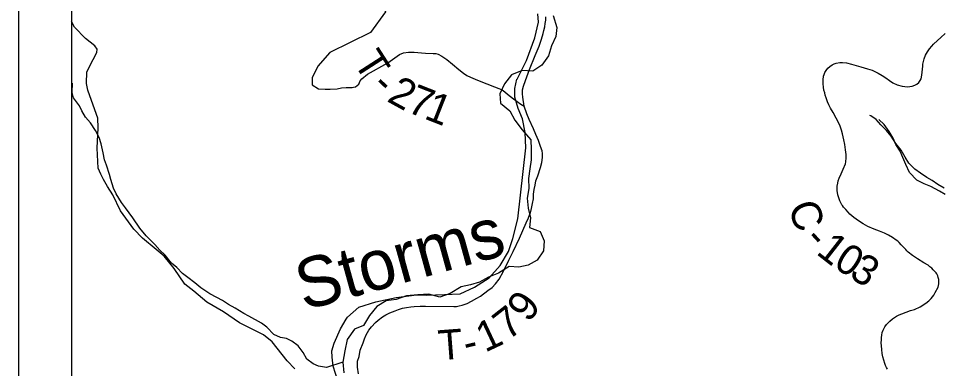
# Model space of a CAD drawing. Extents: x 0 to 34, y 0 to 22.
# Drawn here: x 2 to 3.746, y 18.72 to 19.381 of the extents above; entities that cross this region are included whole.
import ezdxf

# ---------------------------------------------------------------- set-up
doc = ezdxf.new("R2010")
doc.units = 0
for name, color, linetype in [('GM_X_County_Road', 7, 'Continuous'), ('GM_X_County_Road_Text', 7, 'Continuous'), ('GM_X_Minor_River', 7, 'Continuous'), ('GM_X_Minor_River_Text', 7, 'Continuous'), ('GM_X_Rail_Line', 7, 'Continuous'), ('GM_X_Township_Road', 7, 'Continuous'), ('GM_X_Township_Road_Text', 7, 'Continuous'), ('SH_Data', 7, 'Continuous')]:
    doc.layers.add(name, color=color, linetype=linetype)

msp = doc.modelspace()

# ---------------------------------------------------------------- linework, layer by layer
at = {"layer": 'GM_X_County_Road'}
for points in [[(2.5221, 18.7197), (2.5078, 18.7347), (2.4796, 18.7702), (2.4633, 18.7839), (2.4354, 18.7974), (2.4176, 18.8066), (2.3874, 18.8273), (2.356, 18.8454), (2.3315, 18.866), (2.3145, 18.8794), (2.2942, 18.9088), (2.2751, 18.9321), (2.26, 18.9451), (2.2343, 18.9662), (2.2177, 18.9834), (2.1926, 19.0181), (2.178, 19.0482), (2.1682, 19.0642), (2.1607, 19.0772), (2.1555, 19.0871), (2.1506, 19.0985), (2.149, 19.1365), (2.1503, 19.1749), (2.1501, 19.1931), (2.1411, 19.2178), (2.1311, 19.246), (2.1285, 19.2582), (2.129, 19.2802), (2.1409, 19.3037), (2.1479, 19.3169), (2.1487, 19.3234), (2.1441, 19.3299), (2.1268, 19.3433), (2.1061, 19.365), (2.1, 19.3757)], [(3.6422, 18.7185), (3.6403, 18.7218), (3.6386, 18.726), (3.637, 18.7295), (3.6351, 18.7357), (3.6335, 18.7421), (3.6322, 18.7487), (3.6314, 18.7557), (3.6308, 18.7628), (3.6305, 18.7686), (3.6306, 18.7741), (3.6308, 18.7785), (3.6316, 18.7831), (3.6323, 18.7878), (3.6342, 18.7925), (3.6375, 18.7989), (3.6405, 18.8033), (3.6464, 18.8098), (3.6518, 18.814), (3.6552, 18.8164), (3.6595, 18.8189), (3.6643, 18.8214), (3.6696, 18.8235), (3.6855, 18.8294), (3.6932, 18.8316), (3.7041, 18.8366), (3.7147, 18.8434), (3.7203, 18.8479), (3.7245, 18.8523), (3.7296, 18.8583), (3.7325, 18.8638), (3.7377, 18.8737), (3.7393, 18.8799), (3.7393, 18.8841), (3.739, 18.8882), (3.7382, 18.8921), (3.7372, 18.8953), (3.7354, 18.8991), (3.7339, 18.9011), (3.7313, 18.9037), (3.7286, 18.9066), (3.726, 18.9093), (3.7224, 18.9121), (3.7188, 18.9152), (3.7111, 18.9197), (3.6991, 18.9275), (3.6897, 18.9338), (3.6816, 18.9397), (3.6787, 18.9426), (3.6768, 18.9447), (3.6721, 18.9501), (3.6682, 18.954), (3.6642, 18.9581), (3.6615, 18.9607), (3.6584, 18.9628), (3.6518, 18.9677), (3.6444, 18.9717), (3.6363, 18.9757), (3.6272, 18.9794), (3.6171, 18.9833), (3.6049, 18.9885), (3.5964, 18.9932), (3.5873, 18.9989), (3.5784, 19.0051), (3.571, 19.0119), (3.5678, 19.0152), (3.5633, 19.0202), (3.5594, 19.0247), (3.5573, 19.0277), (3.5561, 19.0294), (3.5522, 19.0371), (3.5507, 19.0407), (3.5483, 19.048), (3.5477, 19.0524), (3.5471, 19.0559), (3.547, 19.0599), (3.5472, 19.0645), (3.5482, 19.0701), (3.5492, 19.0743), (3.5511, 19.0797), (3.5546, 19.0879), (3.5587, 19.0964), (3.5626, 19.1068), (3.5632, 19.1105), (3.5641, 19.118), (3.564, 19.1245), (3.563, 19.1332), (3.5614, 19.1431), (3.5598, 19.1523), (3.5573, 19.1634), (3.555, 19.1704), (3.5521, 19.1796), (3.5455, 19.1929), (3.5396, 19.2036), (3.5346, 19.2116), (3.5316, 19.218), (3.5289, 19.2239), (3.5263, 19.2311), (3.5245, 19.2363), (3.5235, 19.2409), (3.5222, 19.246), (3.5215, 19.2514), (3.5209, 19.2578), (3.5207, 19.2653), (3.5215, 19.2721), (3.5225, 19.2754), (3.524, 19.2791), (3.5261, 19.2832), (3.5296, 19.2872), (3.533, 19.2905), (3.5377, 19.2937), (3.5416, 19.2954), (3.5452, 19.2966), (3.552, 19.2979), (3.557, 19.2984), (3.5647, 19.2976), (3.5744, 19.295), (3.5918, 19.2902), (3.6044, 19.2864), (3.6131, 19.2837), (3.6244, 19.2779), (3.6319, 19.2734), (3.6388, 19.2692), (3.646, 19.2642), (3.6526, 19.2599), (3.6607, 19.2559), (3.6701, 19.2532), (3.68, 19.2522), (3.6889, 19.2534), (3.694, 19.2553), (3.6974, 19.2574), (3.7014, 19.2604), (3.7042, 19.264), (3.7057, 19.2672), (3.7072, 19.2745), (3.7079, 19.2798), (3.7088, 19.2912), (3.7093, 19.2952), (3.7102, 19.3003), (3.7114, 19.3048), (3.7143, 19.3117), (3.7181, 19.3186), (3.7219, 19.3242), (3.7258, 19.329), (3.7294, 19.3326), (3.7366, 19.3398), (3.7429, 19.3456), (3.7509, 19.3528)]]:
    msp.add_lwpolyline(points, dxfattribs=at)
at = {"layer": 'GM_X_Minor_River'}
for points in [[(3.0103, 19.3869), (3.0174, 19.3644), (3.0155, 19.3473), (3.0071, 19.3294), (3.0018, 19.3108), (2.9889, 19.2933), (2.9718, 19.2819), (2.9517, 19.2831), (2.9317, 19.2747), (2.9187, 19.2576), (2.9096, 19.239), (2.9111, 19.2215), (2.9285, 19.207), (2.9383, 19.1891), (2.9519, 19.1709), (2.9685, 19.1518), (2.9688, 19.134), (2.9688, 19.1142), (2.9661, 19.0971), (2.9638, 19.0788), (2.9645, 19.0598), (2.9614, 19.0419), (2.9632, 19.0229), (2.9674, 19.005), (2.9658, 18.9867), (2.9859, 18.9787), (2.9934, 18.9612), (2.9922, 18.9426), (2.9804, 18.9247)], [(2.6132, 18.7321), (2.5822, 18.722), (2.5667, 18.7247), (2.5568, 18.7292), (2.5448, 18.738), (2.5383, 18.7505), (2.5285, 18.763), (2.5168, 18.7717), (2.5066, 18.777), (2.4949, 18.7789), (2.4828, 18.7842), (2.4692, 18.7982), (2.4593, 18.8054), (2.4355, 18.8187), (2.4257, 18.824), (2.4094, 18.8339), (2.3966, 18.8411), (2.3856, 18.8483), (2.3751, 18.8543), (2.3614, 18.8612), (2.3448, 18.8725), (2.3335, 18.882), (2.3199, 18.8919), (2.31, 18.8998), (2.2991, 18.9108), (2.2893, 18.9192), (2.2772, 18.9343), (2.2673, 18.9438), (2.2579, 18.9544), (2.2416, 18.9707), (2.2295, 18.9852), (2.2163, 19.0045), (2.2023, 19.0238), (2.1948, 19.0337), (2.1846, 19.05), (2.1797, 19.061), (2.1744, 19.0773), (2.1721, 19.0868), (2.1661, 19.1042), (2.1623, 19.1145), (2.16, 19.1274), (2.1562, 19.1448), (2.1525, 19.1566), (2.1453, 19.1699), (2.1362, 19.1843), (2.1264, 19.1949), (2.1196, 19.2067), (2.1151, 19.2165), (2.1041, 19.2317), (2.1015, 19.2415), (2.1022, 19.2594)], [(3.7491, 19.0608), (3.7374, 19.0677), (3.7265, 19.0753), (3.7163, 19.0807), (3.7045, 19.0891), (3.694, 19.0967), (3.6823, 19.1077), (3.6755, 19.1191), (3.6683, 19.1324), (3.6581, 19.1454), (3.6491, 19.1591), (3.6404, 19.1697), (3.6298, 19.1804), (3.6208, 19.1903), (3.611, 19.1975), (3.6091, 19.1983)], [(3.751, 19.0488), (3.7405, 19.0552), (3.7242, 19.0639), (3.7117, 19.0692), (3.6977, 19.076), (3.6841, 19.0904), (3.6766, 19.1052), (3.6713, 19.1185), (3.666, 19.1306), (3.6581, 19.1435), (3.6528, 19.1549), (3.6456, 19.1678), (3.6358, 19.1811), (3.6257, 19.1906)], [(2.9804, 18.9247), (2.9634, 18.9152), (2.9456, 18.9118), (2.927, 18.9126), (2.9073, 18.9004), (2.8884, 18.8928), (2.8713, 18.8833), (2.8543, 18.878), (2.8368, 18.8742), (2.816, 18.8617), (2.7963, 18.8549), (2.7755, 18.8602), (2.7547, 18.8595), (2.7331, 18.8576), (2.7138, 18.8504), (2.6948, 18.8477), (2.677, 18.8375), (2.6633, 18.8203), (2.6523, 18.8013), (2.6353, 18.7945), (2.6212, 18.7747), (2.6166, 18.7534), (2.6132, 18.7321), (2.615, 18.7116)]]:
    msp.add_lwpolyline(points, dxfattribs=at)
at = {"layer": 'GM_X_Rail_Line'}
msp.add_lwpolyline([(2.6037, 18.697), (2.5949, 18.7243), (2.5928, 18.7415), (2.5922, 18.7534), (2.5963, 18.7678), (2.6085, 18.7949), (2.6192, 18.813), (2.622, 18.8173), (2.6431, 18.8359), (2.6751, 18.8459), (2.7137, 18.8542), (2.7524, 18.8593), (2.7708, 18.8588), (2.8053, 18.8598), (2.8345, 18.8609), (2.8618, 18.8738), (2.8892, 18.8915), (2.9101, 18.9149), (2.9262, 18.9414), (2.9342, 18.9656), (2.9435, 19.0028), (2.9587, 19.1369), (2.9573, 19.1659), (2.9522, 19.1918), (2.9444, 19.2115), (2.9382, 19.2329), (2.9377, 19.2488), (2.9417, 19.2665), (2.9423, 19.2667), (2.9599, 19.3018), (2.9759, 19.345), (2.9825, 19.3745), (2.9817, 19.3898)], dxfattribs=at)
at = {"layer": 'GM_X_Township_Road'}
for points in [[(2.6897, 19.4018), (2.6937, 19.3937), (2.6653, 19.3545), (2.5886, 19.3171), (2.5654, 19.2909), (2.5551, 19.269), (2.5548, 19.2559), (2.5672, 19.2485), (2.5795, 19.2478), (2.5888, 19.2478), (2.602, 19.2486), (2.6102, 19.2504), (2.6192, 19.251), (2.6303, 19.251), (2.6329, 19.2514)], [(2.6427, 18.7102), (2.6409, 18.7224), (2.6407, 18.734), (2.6436, 18.7428), (2.6459, 18.7544), (2.6515, 18.7684), (2.6538, 18.7764), (2.6568, 18.7838), (2.6623, 18.7926), (2.6671, 18.7985), (2.6748, 18.8069), (2.68, 18.8116), (2.6876, 18.8174), (2.6944, 18.8215), (2.7017, 18.8254), (2.7118, 18.8292), (2.7181, 18.8315), (2.7255, 18.8338), (2.7335, 18.8356), (2.7412, 18.8368), (2.7479, 18.8374), (2.7591, 18.8376), (2.7692, 18.8377), (2.8229, 18.8373), (2.8277, 18.8375), (2.8325, 18.8384), (2.8384, 18.8397), (2.8479, 18.8431), (2.8558, 18.8473), (2.866, 18.8529), (2.8731, 18.8569), (2.8872, 18.8672), (2.8952, 18.8732), (2.9014, 18.8798), (2.9084, 18.8887), (2.9166, 18.9042), (2.9266, 18.925), (2.9348, 18.941), (2.9467, 18.9661), (2.9597, 18.9952), (2.9638, 19.0048), (2.9671, 19.0133), (2.9674, 19.0142), (2.9695, 19.0224), (2.9715, 19.0319), (2.9732, 19.0407), (2.9735, 19.0492), (2.9747, 19.0585), (2.9761, 19.0662), (2.9779, 19.0746), (2.9813, 19.0843), (2.9864, 19.0997), (2.9891, 19.1092), (2.99, 19.1188), (2.9901, 19.126), (2.9894, 19.1311), (2.9867, 19.1396), (2.9827, 19.1505), (2.9778, 19.1624), (2.9733, 19.1729), (2.965, 19.1903), (2.9606, 19.201), (2.9559, 19.2158), (2.953, 19.2325), (2.9522, 19.239), (2.9523, 19.2462), (2.9543, 19.2536), (2.958, 19.2643), (2.966, 19.2847), (2.9762, 19.3111), (2.9837, 19.3292), (2.9883, 19.342), (2.9915, 19.353), (2.9929, 19.3585), (2.9945, 19.3654), (2.9956, 19.3721), (2.9965, 19.378), (2.9964, 19.3843)], [(2.6329, 19.2514), (2.6367, 19.2519), (2.6431, 19.2574), (2.6457, 19.2634), (2.6487, 19.2673), (2.6598, 19.2758), (2.6979, 19.2977), (2.7203, 19.3132), (2.7278, 19.3166), (2.737, 19.3179), (2.7478, 19.3174), (2.7613, 19.3165), (2.7693, 19.3157), (2.7837, 19.3154), (2.7884, 19.315), (2.7932, 19.3138), (2.8, 19.3104), (2.8093, 19.3037), (2.8204, 19.2948), (2.832, 19.2851), (2.8411, 19.2782), (2.8471, 19.2736), (2.8544, 19.2702), (2.8629, 19.2665), (2.8738, 19.262), (2.8853, 19.2576), (2.8998, 19.252), (2.9076, 19.249), (2.9139, 19.2462), (2.9191, 19.2428), (2.9244, 19.2384), (2.9357, 19.2296), (2.9492, 19.2195), (2.9559, 19.2158)]]:
    msp.add_lwpolyline(points, dxfattribs=at)
at = {"layer": 'SH_Data'}
for p, q in [((2, 21), (2, 14)), ((2.1, 20.9), (2.1, 14.1))]:
    msp.add_line(p, q, dxfattribs=at)

# ---------------------------------------------------------------- texts
at = {"layer": 'GM_X_County_Road_Text'}
for s, rotation, p in [('C', 291.2433, (3.4531, 19.0248)), ('-', 312.4996, (3.4821, 18.9619)), ('1', 322.0635, (3.5055, 18.9376)), ('0', 327.5759, (3.5379, 18.9127)), ('3', 327.5821, (3.5675, 18.8939))]:
    msp.add_text(s, height=0.0568, rotation=rotation, dxfattribs=at).set_placement(p)
at = {"layer": 'GM_X_Minor_River_Text'}
msp.add_text('Storms', height=0.0947, rotation=15.5032, dxfattribs=at).set_placement((2.5392, 18.8291))
at = {"layer": 'GM_X_Township_Road_Text'}
for s, rotation, p in [('T', 302.6963, (2.6318, 19.2984)), ('-', 317.0271, (2.6646, 19.2507)), ('2', 331.3579, (2.6943, 19.2258)), ('7', 338.5233, (2.732, 19.2057)), ('1', 338.5233, (2.7646, 19.1929)), ('9', 52.8673, (2.964, 18.8049)), ('7', 38.0141, (2.9252, 18.7719)), ('1', 25.169, (2.8817, 18.7497)), ('T', 4.3593, (2.795, 18.7354)), ('-', 13.3938, (2.847, 18.7401))]:
    msp.add_text(s, height=0.0568, rotation=rotation, dxfattribs=at).set_placement(p)

doc.saveas('drawing.dxf')
